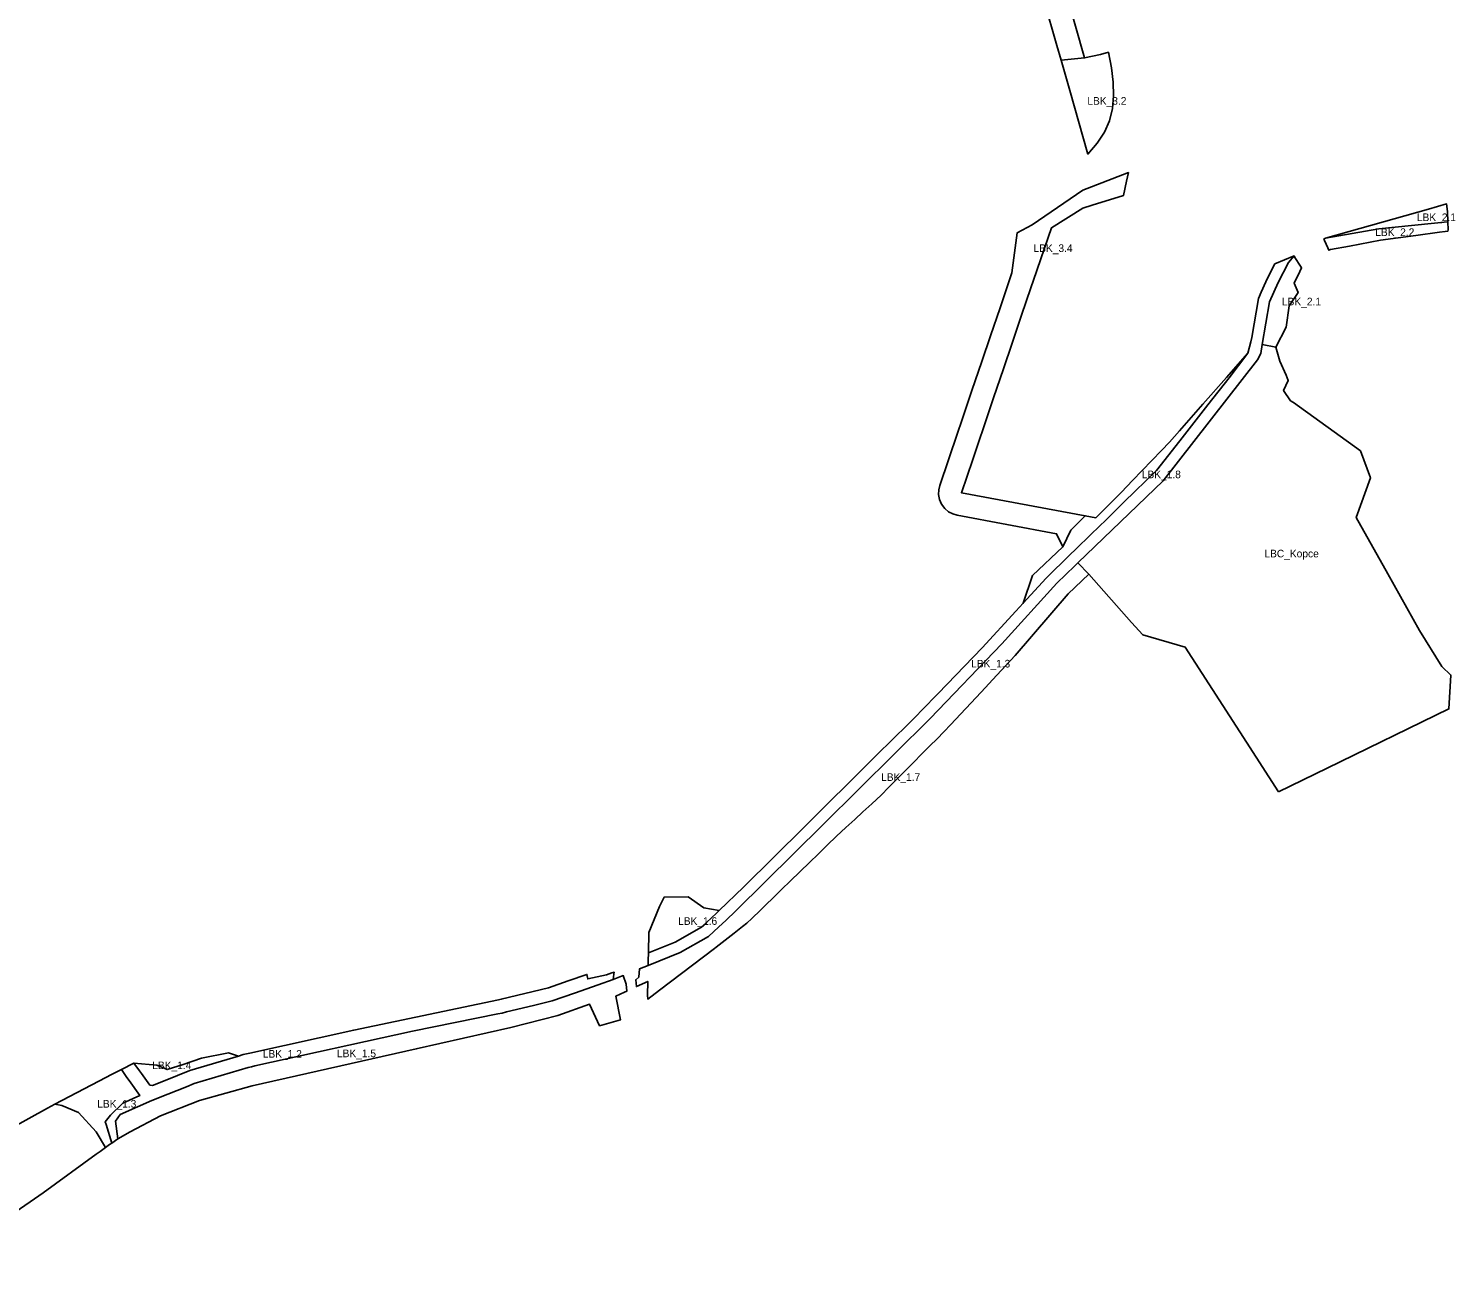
# Model space of a CAD drawing. Extents: x -535894 to -532763, y -1165802 to -1163647.
# Drawn here: x -534659 to -533722, y -1165546 to -1164727 of the extents above; entities that cross this region are included whole.
import ezdxf

# ---------------------------------------------------------------- set-up
doc = ezdxf.new("R2010")
doc.units = 0
for name, color, linetype in [('91270013', 7, 'Continuous'), ('91280013', 7, 'Continuous'), ('91280023', 7, 'Continuous')]:
    doc.layers.add(name, color=color, linetype=linetype)

msp = doc.modelspace()

# ---------------------------------------------------------------- linework, layer by layer
at = {"layer": '91270013'}
msp.add_lwpolyline([(-533837.937, -1165228.09), (-533859.04, -1165195.4), (-533899.27, -1165133.08), (-533927.15, -1165125.06), (-533934.45, -1165116.87), (-533962.53, -1165085.32), (-533969.698, -1165077.779), (-533913.79, -1165024.04), (-533851.83, -1164944.65), (-533849.69, -1164940.46), (-533848.679, -1164934.441), (-533839.74, -1164936.26), (-533838.84, -1164939.32), (-533837.05, -1164945.36), (-533833.05, -1164954.72), (-533831.57, -1164958.17), (-533834.67, -1164964.81), (-533830.03, -1164971.49), (-533828.25, -1164972.65), (-533784.18, -1165004.34), (-533777.72, -1165022.03), (-533786.95, -1165048.06), (-533766.306, -1165084.954), (-533745.52, -1165122.1), (-533730.88, -1165145.85), (-533724.81, -1165151.41), (-533726.09, -1165173.68), (-533806.07, -1165212.59)], close=True, dxfattribs=at)
at = {"layer": '91280013'}
for points in [[(-533965.282, -1164746.513), (-533954.82, -1164744.13), (-533949.63, -1164742.72), (-533947.667, -1164752.915), (-533946.509, -1164762.433), (-533946.273, -1164771.351), (-533947.08, -1164779.742), (-533949.047, -1164787.683), (-533952.293, -1164795.247), (-533956.938, -1164802.511), (-533963.1, -1164809.55), (-533974.92, -1164767.93), (-533980.66, -1164747.97)], [(-533772.11, -1164858.69), (-533727.16, -1164854.1), (-533726.9, -1164854), (-533726.73, -1164859.25), (-533726.94, -1164860.18), (-533728.63, -1164860.41), (-533732.38, -1164860.92), (-533747.79, -1164863), (-533771.09, -1164866.14), (-533791.44, -1164869.9), (-533803.9, -1164872.2), (-533804.975, -1164872.651), (-533805.67, -1164871.11), (-533807.83, -1164866.32), (-533808.265, -1164865.356), (-533807.19, -1164864.79)], [(-533838.18, -1164893.83), (-533831.54, -1164880.79), (-533827.73, -1164876.4), (-533827.39, -1164877.5), (-533823.63, -1164883.1), (-533822.83, -1164884.292), (-533825.17, -1164889.09), (-533825.28, -1164889.29), (-533827.81, -1164894.29), (-533825.11, -1164900.3), (-533831.01, -1164909.18), (-533832.91, -1164923.14), (-533839.74, -1164936.26), (-533848.679, -1164934.441), (-533843.98, -1164906.47)], [(-533990.612, -1165087.806), (-534005.544, -1165104.269), (-533999.48, -1165086.16), (-533979.67, -1165067.29), (-533974.3, -1165056.33), (-533964.89, -1165046.93), (-533958, -1165048.21), (-533949.192, -1165039.528), (-533943.27, -1165033.69), (-533941.12, -1165031.45), (-533933.76, -1165023.78), (-533914.87, -1165004.11), (-533909.61, -1164998.62), (-533903.09, -1164991.22), (-533887.6, -1164973.66), (-533872.1, -1164956.08), (-533858.16, -1164940.26), (-533870.466, -1164956.339), (-533884.317, -1164974.086), (-533898.225, -1164991.906), (-533902.835, -1164997.813), (-533917.983, -1165017.223), (-533939.32, -1165037.78), (-533948.251, -1165046.797), (-533950.892, -1165049.339), (-533960.954, -1165059.022), (-533971.32, -1165068.999), (-533974.832, -1165072.379)], [(-533962.53, -1165085.32), (-533976.02, -1165098.2), (-534010.91, -1165138.64), (-534022.96, -1165151.54), (-534033.26, -1165162.58), (-534053.42, -1165184.18), (-534057.5, -1165188.56), (-534062.36, -1165193.44), (-534066.63, -1165197.75), (-534069.42, -1165200.54), (-534080.31, -1165211.51), (-534083.69, -1165214.91), (-534088.44, -1165219.7), (-534093.73, -1165225.02), (-534098.91, -1165230.23), (-534105.03, -1165235.88), (-534110.88, -1165241.27), (-534116.12, -1165246.09), (-534121.92, -1165251.44), (-534128.1, -1165257.13), (-534128.78, -1165257.75), (-534133.62, -1165262.47), (-534140, -1165268.66), (-534145.91, -1165274.41), (-534151.99, -1165280.33), (-534158.49, -1165286.65), (-534163.98, -1165291.99), (-534169.57, -1165297.42), (-534174.7, -1165302.41), (-534178, -1165305.62), (-534183.78, -1165311.24), (-534186.9, -1165314.27), (-534189.75, -1165316.48), (-534195.4, -1165320.86), (-534201.15, -1165325.32), (-534207.06, -1165329.91), (-534208.23, -1165330.82), (-534244.32, -1165358.176), (-534251.99, -1165363.99), (-534252.23, -1165361.54), (-534252.01, -1165352.47), (-534259.48, -1165355.88), (-534259.96, -1165351.32), (-534257.97, -1165349.66), (-534257.49, -1165344.29), (-534251.77, -1165341.96), (-534230.69, -1165333.38), (-534212.27, -1165323.02), (-534205.31, -1165316.61), (-534200.89, -1165312.54), (-534194.29, -1165306.12), (-534136.8, -1165249.37), (-534066.72, -1165179.82), (-534019.59, -1165130.92), (-533983.52, -1165091.15), (-533971.79, -1165079.79), (-533969.698, -1165077.779)], [(-534205.1, -1165305.987), (-534206.827, -1165307.611), (-534213.437, -1165313.824), (-534213.981, -1165314.335), (-534216.742, -1165316.93), (-534233.955, -1165326.611), (-534251.577, -1165333.784), (-534251.27, -1165320.44), (-534244.31, -1165303.28), (-534241.33, -1165297.17), (-534225.42, -1165296.87), (-534215.31, -1165304.06)], [(-534598.29, -1165439.76), (-534577.5, -1165430.58), (-534567.01, -1165426.39), (-534554.75, -1165421.51), (-534549.73, -1165419.5), (-534514.4, -1165408.9), (-534512.18, -1165408.41), (-534509.97, -1165407.93), (-534406.37, -1165385.09), (-534350.42, -1165373.76), (-534347.57, -1165373.21), (-534344.67, -1165372.49), (-534327.1, -1165368.26), (-534314.72, -1165365.27), (-534300.23, -1165360.21), (-534284.53, -1165354.73), (-534274.64, -1165351.27), (-534268.13, -1165348.62), (-534266.24, -1165354.33), (-534265.74, -1165358.75), (-534267.32, -1165359.47), (-534272.9, -1165362.02), (-534269.895, -1165377.58), (-534283.614, -1165381.526), (-534290.38, -1165367.27), (-534311.13, -1165374.91), (-534341.94, -1165382.62), (-534404.04, -1165396.72), (-534511.63, -1165420.88), (-534546.3, -1165430.52), (-534571.82, -1165440.57), (-534591.82, -1165451.2), (-534599.87, -1165455.71), (-534601.363, -1165444.1)], [(-534578.843, -1165420.532), (-534584.327, -1165412.961), (-534585.708, -1165411.053), (-534589.332, -1165406.049), (-534574.28, -1165407.33), (-534570.57, -1165408.93), (-534567.43, -1165410.29), (-534557.01, -1165406.86), (-534544.87, -1165402.87), (-534527.22, -1165399.28), (-534520.704, -1165401.395), (-534552.702, -1165410.995), (-534568.837, -1165417.43), (-534577.132, -1165420.742)], [(-534614.062, -1165451.061), (-534625.805, -1165438.391), (-534636.67, -1165433.924), (-534641.319, -1165433.008), (-534612.41, -1165417.8), (-534603.53, -1165413.28), (-534597.581, -1165410.25), (-534593.887, -1165415.471), (-534592.444, -1165417.51), (-534585.468, -1165427.37), (-534596.584, -1165432.419), (-534599.518, -1165435.213), (-534601.568, -1165437.166), (-534604.649, -1165440.099), (-534608.122, -1165444.506), (-534607.549, -1165446.401), (-534603.882, -1165458.535), (-534605.28, -1165459.52), (-534607.908, -1165461.42)]]:
    msp.add_lwpolyline(points, close=True, dxfattribs=at)
at = {"layer": '91280023'}
for points in [[(-533992.01, -1164708.4), (-533996.002, -1164692.697), (-534004.077, -1164694.939), (-533998.16, -1164689.6), (-533997.187, -1164688.034), (-533991.85, -1164679.44), (-533986.32, -1164682.27), (-533978.18, -1164703.55), (-533976.638, -1164706.229), (-533965.282, -1164746.513), (-533980.66, -1164747.97), (-533983.41, -1164738.37)], [(-533966.36, -1164833.16), (-533960.78, -1164831.03), (-533936.53, -1164821.76), (-533937.75, -1164827.32), (-533939.824, -1164836.771), (-533960.22, -1164843.182), (-533966.45, -1164845.14), (-533986.98, -1164857.88), (-533998.79, -1164892.25), (-534000.56, -1164897.43), (-534006.6, -1164915.2), (-534012.88, -1164933.73), (-534018.61, -1164950.58), (-534025.02, -1164969.45), (-534031.7, -1164989.14), (-534034.52, -1164997.43), (-534038.74, -1165009.878), (-534046.172, -1165031.796), (-533964.89, -1165046.93), (-533974.3, -1165056.33), (-533979.67, -1165067.29), (-533983.719, -1165058.682), (-534048.917, -1165046.543), (-534051.748, -1165045.721), (-534054.541, -1165044.245), (-534057.072, -1165042.101), (-534059.114, -1165039.378), (-534060.49, -1165036.266), (-534061.122, -1165033.009), (-534061.045, -1165029.851), (-534060.377, -1165026.98), (-534048.723, -1164992.607), (-534045.903, -1164984.315), (-534039.224, -1164964.628), (-534032.812, -1164945.753), (-534027.084, -1164928.908), (-534020.803, -1164910.376), (-534012.983, -1164887.396), (-534009.46, -1164861.214), (-533999.79, -1164855.92)], [(-533739.473, -1164845.641), (-533727.669, -1164842.303), (-533727.12, -1164847.21), (-533726.9, -1164854), (-533727.16, -1164854.1), (-533772.11, -1164858.69), (-533807.19, -1164864.79)], [(-533849.69, -1164940.46), (-533851.83, -1164944.65), (-533913.79, -1165024.04), (-533969.698, -1165077.779), (-533971.79, -1165079.79), (-533983.52, -1165091.15), (-534019.59, -1165130.92), (-534066.72, -1165179.82), (-534136.8, -1165249.37), (-534194.29, -1165306.12), (-534200.89, -1165312.54), (-534205.31, -1165316.61), (-534212.27, -1165323.02), (-534230.69, -1165333.38), (-534251.77, -1165341.96), (-534251.69, -1165338.72), (-534251.577, -1165333.784), (-534233.955, -1165326.611), (-534216.742, -1165316.93), (-534213.981, -1165314.335), (-534213.437, -1165313.824), (-534206.827, -1165307.611), (-534205.1, -1165305.987), (-534189.229, -1165290.586), (-534149.077, -1165250.937), (-534139.471, -1165241.41), (-534114.175, -1165216.322), (-534101.588, -1165203.839), (-534081.184, -1165183.602), (-534078.555, -1165180.995), (-534075.928, -1165178.389), (-534072.062, -1165174.555), (-534061.508, -1165163.605), (-534032.625, -1165133.636), (-534010.382, -1165109.604), (-534005.544, -1165104.269), (-533990.612, -1165087.806), (-533974.832, -1165072.379), (-533971.32, -1165068.999), (-533960.954, -1165059.022), (-533950.892, -1165049.339), (-533948.251, -1165046.797), (-533939.32, -1165037.78), (-533917.983, -1165017.223), (-533902.835, -1164997.813), (-533898.225, -1164991.906), (-533884.317, -1164974.086), (-533870.466, -1164956.339), (-533858.16, -1164940.26), (-533856.252, -1164932.754), (-533855.511, -1164929.84), (-533851.211, -1164904.246), (-533849.336, -1164900.158), (-533846.247, -1164893.426), (-533845.178, -1164891.097), (-533840.359, -1164881.598), (-533827.73, -1164876.4), (-533831.54, -1164880.79), (-533838.18, -1164893.83), (-533843.98, -1164906.47), (-533848.679, -1164934.441)], [(-534592.444, -1165417.51), (-534593.887, -1165415.471), (-534597.581, -1165410.25), (-534589.332, -1165406.049), (-534585.708, -1165411.053), (-534584.327, -1165412.961), (-534578.843, -1165420.532), (-534577.132, -1165420.742), (-534568.837, -1165417.43), (-534552.702, -1165410.995), (-534520.704, -1165401.395), (-534517.583, -1165400.459), (-534513.151, -1165399.411), (-534444.988, -1165384.388), (-534349.958, -1165364.505), (-534348.18, -1165364.088), (-534317.266, -1165356.626), (-534304.229, -1165352.074), (-534292.023, -1165347.813), (-534291.425, -1165350.782), (-534279.12, -1165348.18), (-534275.59, -1165346.89), (-534274.043, -1165346.403), (-534274.2, -1165347.69), (-534274.64, -1165351.27), (-534284.53, -1165354.73), (-534300.23, -1165360.21), (-534314.72, -1165365.27), (-534327.1, -1165368.26), (-534344.67, -1165372.49), (-534347.57, -1165373.21), (-534350.42, -1165373.76), (-534406.37, -1165385.09), (-534509.97, -1165407.93), (-534512.18, -1165408.41), (-534514.4, -1165408.9), (-534549.73, -1165419.5), (-534554.75, -1165421.51), (-534567.01, -1165426.39), (-534577.5, -1165430.58), (-534598.29, -1165439.76), (-534601.363, -1165444.1), (-534599.87, -1165455.71), (-534603.882, -1165458.535), (-534607.549, -1165446.401), (-534608.122, -1165444.506), (-534604.649, -1165440.099), (-534601.568, -1165437.166), (-534599.518, -1165435.213), (-534596.584, -1165432.419), (-534585.468, -1165427.37)]]:
    msp.add_lwpolyline(points, close=True, dxfattribs=at)
msp.add_lwpolyline([(-534721.707, -1165477.481), (-534646.155, -1165435.684), (-534641.319, -1165433.008), (-534636.67, -1165433.924), (-534625.805, -1165438.391), (-534614.062, -1165451.061), (-534607.908, -1165461.42), (-534611.57, -1165464.068), (-534614.01, -1165465.833), (-534648.91, -1165491.07), (-534728.46, -1165546.03)], dxfattribs=at)

# ---------------------------------------------------------------- texts
at = {"layer": '91270013'}
msp.add_text('LBC_Kopce', height=5, rotation=360, dxfattribs=at).set_placement((-533847.254, -1165074.1941))
at = {"layer": '91280013'}
for s, rotation, p in [('LBK_3.2', 360, (-533963.4665, -1164777.1795)), ('LBK_2.2', 0, (-533774.4866, -1164863.3255)), ('LBK_2.1', 0.0000001, (-533835.7545, -1164908.8354)), ('LBK_1.8', 359.9999999, (-533927.7602, -1165022.2645)), ('LBK_1.6', 0, (-534232.1163, -1165315.327)), ('LBK_1.5', 0, (-534456.0542, -1165402.165)), ('LBK_1.4', 0.0000001, (-534577.2684, -1165410.011)), ('LBK_1.3', 0, (-534613.3935, -1165435.2518))]:
    msp.add_text(s, height=5, rotation=rotation, dxfattribs=at).set_placement(p)
msp.add_text('LBK_1.7', height=5, dxfattribs=at).set_placement((-534098.8576, -1165220.8845))
at = {"layer": '91280023'}
for s, rotation, p in [('LBK_2.1', 0, (-533747.172, -1164853.5465)), ('LBK_3.4', 0, (-533998.826, -1164873.8095)), ('LBK_1.3', 0, (-534039.75, -1165146.433)), ('LBK_1.2', 360, (-534504.7416, -1165402.469))]:
    msp.add_text(s, height=5, rotation=rotation, dxfattribs=at).set_placement(p)

doc.saveas('drawing.dxf')
